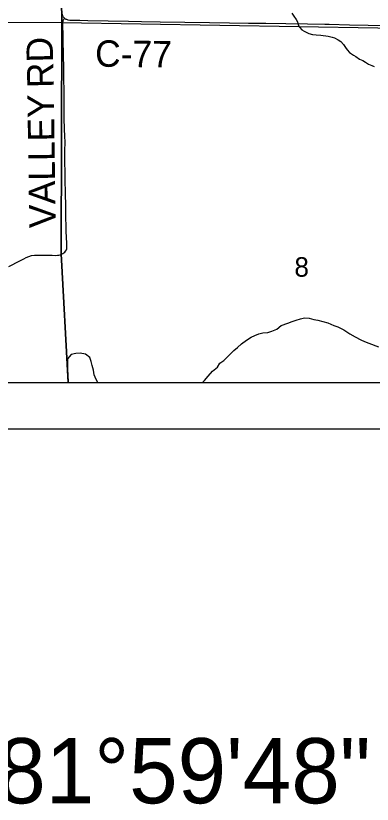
# Model space of a CAD drawing. Extents: x 0 to 34, y 0 to 22.
# Drawn here: x 6.742 to 7.507, y 13.194 to 14.887 of the extents above; entities that cross this region are included whole.
import ezdxf

# ---------------------------------------------------------------- set-up
doc = ezdxf.new("R2010")
doc.units = 0
for name, color, linetype in [('Default', 7, 'Continuous'), ('GM_X_County_Road', 7, 'Continuous'), ('GM_X_County_Road_Text', 7, 'Continuous'), ('GM_X_Minor_River', 7, 'Continuous'), ('GM_X_Section', 7, 'Continuous'), ('GM_X_Section_Text', 7, 'Continuous'), ('GM_X_State_Route', 7, 'Continuous'), ('GM_X_Township_Road', 7, 'Continuous'), ('GM_X_Township_Road_Text', 7, 'Continuous'), ('SH_Data', 7, 'Continuous'), ('SH_Text', 7, 'Continuous')]:
    doc.layers.add(name, color=color, linetype=linetype)

msp = doc.modelspace()

# ---------------------------------------------------------------- linework, layer by layer
at = {"layer": 'Default'}
for points in [[(5.6382, 14.1), (6.8542, 14.1), (6.8396, 14.3761), (6.8411, 14.8726), (5.6415, 14.8783)], [(6.8542, 14.1), (7.8747, 14.1), (7.8581, 14.855), (6.8411, 14.8726), (6.8396, 14.3761)]]:
    msp.add_lwpolyline(points, close=True, dxfattribs=at)
at = {"layer": 'GM_X_County_Road'}
for points in [[(6.8466, 14.8823), (6.8458, 14.8831), (6.8451, 14.8838), (6.8446, 14.8845), (6.8439, 14.8855), (6.8432, 14.8867), (6.8426, 14.8881), (6.842, 14.8898), (6.8416, 14.8913), (6.8412, 14.8942), (6.8409, 14.9002), (6.841, 14.9095), (6.8411, 14.956), (6.8409, 14.9747), (6.8408, 14.9965), (6.8403, 15.0307), (6.8395, 15.068), (6.8391, 15.0897), (6.8387, 15.1176), (6.8383, 15.1673), (6.8382, 15.1733), (6.8381, 15.1806)], [(6.7273, 14.3488), (6.7509, 14.361), (6.7591, 14.3657), (6.7645, 14.3685), (6.7696, 14.3705), (6.7756, 14.3722), (6.7822, 14.3732), (6.7889, 14.3735), (6.7977, 14.3734), (6.8074, 14.3733), (6.814, 14.3732), (6.82, 14.3729), (6.8264, 14.3726), (6.8313, 14.3729), (6.8342, 14.3734), (6.8375, 14.3741), (6.8403, 14.3751), (6.8429, 14.3765), (6.8451, 14.3779), (6.847, 14.3796), (6.8489, 14.3815), (6.8505, 14.3844), (6.8512, 14.3869), (6.8515, 14.391), (6.8515, 14.3982), (6.8501, 14.425), (6.8494, 14.4646), (6.8492, 14.4832), (6.849, 14.5011), (6.8485, 14.5147), (6.8479, 14.5267), (6.8478, 14.539), (6.8476, 14.5546), (6.8473, 14.5701), (6.8474, 14.5794), (6.8474, 14.5977), (6.8477, 14.6161), (6.8473, 14.6288), (6.8466, 14.6441), (6.8456, 14.6672), (6.8455, 14.6818), (6.8456, 14.6937), (6.8458, 14.7059), (6.8456, 14.7263), (6.8451, 14.7523), (6.8448, 14.78), (6.8444, 14.7976), (6.8441, 14.8114), (6.8438, 14.8269), (6.8434, 14.8485), (6.8431, 14.8637), (6.843, 14.8675), (6.8431, 14.8724), (6.8433, 14.875), (6.8439, 14.8772), (6.8442, 14.8787), (6.8448, 14.8801), (6.8456, 14.8811), (6.8466, 14.8823)], [(6.8466, 14.8823), (6.8482, 14.8812), (6.8494, 14.8805), (6.8508, 14.8799), (6.8536, 14.879), (6.8579, 14.8781), (6.864, 14.8778), (6.8688, 14.8777), (6.8791, 14.8778), (6.8968, 14.8773), (6.9403, 14.8766), (6.9838, 14.8758), (7.0117, 14.8753), (7.0521, 14.8747), (7.1048, 14.8739), (7.1576, 14.8731), (7.201, 14.8726), (7.2414, 14.8719), (7.2786, 14.8714), (7.3219, 14.8708), (7.3683, 14.8699), (7.4056, 14.8693), (7.4149, 14.8692), (7.4583, 14.8681), (7.4986, 14.8673), (7.5296, 14.8666)]]:
    msp.add_lwpolyline(points, dxfattribs=at)
at = {"layer": 'GM_X_Minor_River'}
for points in [[(7.3345, 14.8929), (7.339, 14.8868), (7.344, 14.8796), (7.3466, 14.8742), (7.3478, 14.8681), (7.3508, 14.8628), (7.3557, 14.8575), (7.3607, 14.8544), (7.3656, 14.8522), (7.3713, 14.8491), (7.3788, 14.8472), (7.3868, 14.8464), (7.397, 14.8456), (7.4019, 14.8449), (7.4072, 14.8441), (7.4129, 14.8433), (7.4213, 14.8418), (7.4262, 14.8403), (7.4338, 14.8361), (7.4395, 14.8323), (7.4455, 14.8254), (7.4497, 14.819), (7.4531, 14.814), (7.4584, 14.8087), (7.4668, 14.803), (7.4717, 14.7999), (7.48, 14.7946), (7.4872, 14.7912), (7.4925, 14.7881), (7.499, 14.7835), (7.5062, 14.7805), (7.5115, 14.7782)], [(7.143, 14.1), (7.1474, 14.1039), (7.1546, 14.1133), (7.1641, 14.124), (7.175, 14.1327), (7.1799, 14.141), (7.1886, 14.1471), (7.2098, 14.1684), (7.2181, 14.1752), (7.2268, 14.1828), (7.2374, 14.1907), (7.2469, 14.1968), (7.2552, 14.201), (7.2635, 14.2044), (7.2726, 14.2066), (7.2832, 14.207), (7.2919, 14.21), (7.3021, 14.2142), (7.3116, 14.2222), (7.3263, 14.2275), (7.3354, 14.2305), (7.3441, 14.2339), (7.3528, 14.2365), (7.3615, 14.2384), (7.3721, 14.238), (7.382, 14.2353), (7.3903, 14.2334), (7.4013, 14.2308), (7.4119, 14.2277), (7.4244, 14.222), (7.4331, 14.2193), (7.446, 14.2132), (7.4589, 14.2044), (7.4703, 14.1976), (7.4824, 14.1915), (7.4907, 14.188), (7.4995, 14.1839), (7.5207, 14.1766)], [(6.9182, 14.1), (6.9145, 14.1065), (6.9104, 14.1164), (6.9085, 14.1259), (6.9062, 14.1366), (6.9039, 14.1449), (6.9012, 14.1537), (6.8914, 14.1605), (6.8804, 14.1628), (6.8705, 14.1617), (6.8611, 14.1598), (6.8531, 14.1503), (6.8532, 14.1279), (6.8539, 14.1161), (6.8546, 14.1)]]:
    msp.add_lwpolyline(points, dxfattribs=at)
at = {"layer": 'GM_X_Section'}
for points in [[(6.8272, 15.8734), (6.8411, 14.8726), (5.6415, 14.8783), (5.6379, 15.8781), (6.7969, 15.8732)], [(6.8272, 15.8734), (7.8036, 15.873), (7.8312, 15.8725), (7.8581, 14.855), (6.8411, 14.8726)]]:
    msp.add_lwpolyline(points, close=True, dxfattribs=at)
at = {"layer": 'GM_X_State_Route'}
msp.add_lwpolyline([(7.8042, 16.2626), (7.8024, 15.8725), (6.7968, 15.8774), (5.6416, 15.8841), (5.6436, 15.468), (5.6455, 14.1), (8.9, 14.1), (8.9, 18.8876), (8.7984, 18.8872), (8.8033, 17.8763), (8.296, 17.8766), (7.7904, 17.865), (7.8038, 16.9797), (7.9972, 16.9797), (7.9972, 16.2626)], close=True, dxfattribs=at)
at = {"layer": 'GM_X_Township_Road'}
for points in [[(6.8466, 14.8823), (6.8458, 14.8831), (6.8451, 14.8838), (6.8446, 14.8845), (6.8439, 14.8855), (6.8432, 14.8867), (6.8426, 14.8881), (6.842, 14.8898), (6.8416, 14.8913), (6.8412, 14.8942), (6.8409, 14.9002), (6.841, 14.9095), (6.8411, 14.956), (6.8409, 14.9747), (6.8408, 14.9965), (6.8403, 15.0307), (6.8395, 15.068), (6.8391, 15.0897), (6.8387, 15.1176), (6.8383, 15.1673), (6.8382, 15.1733), (6.8381, 15.1806)], [(6.7273, 14.3488), (6.7509, 14.361), (6.7591, 14.3657), (6.7645, 14.3685), (6.7696, 14.3705), (6.7756, 14.3722), (6.7822, 14.3732), (6.7889, 14.3735), (6.7977, 14.3734), (6.8074, 14.3733), (6.814, 14.3732), (6.82, 14.3729), (6.8264, 14.3726), (6.8313, 14.3729), (6.8342, 14.3734), (6.8375, 14.3741), (6.8403, 14.3751), (6.8429, 14.3765), (6.8451, 14.3779), (6.847, 14.3796), (6.8489, 14.3815), (6.8505, 14.3844), (6.8512, 14.3869), (6.8515, 14.391), (6.8515, 14.3982), (6.8501, 14.425), (6.8494, 14.4646), (6.8492, 14.4832), (6.849, 14.5011), (6.8485, 14.5147), (6.8479, 14.5267), (6.8478, 14.539), (6.8476, 14.5546), (6.8473, 14.5701), (6.8474, 14.5794), (6.8474, 14.5977), (6.8477, 14.6161), (6.8473, 14.6288), (6.8466, 14.6441), (6.8456, 14.6672), (6.8455, 14.6818), (6.8456, 14.6937), (6.8458, 14.7059), (6.8456, 14.7263), (6.8451, 14.7523), (6.8448, 14.78), (6.8444, 14.7976), (6.8441, 14.8114), (6.8438, 14.8269), (6.8434, 14.8485), (6.8431, 14.8637), (6.843, 14.8675), (6.8431, 14.8724), (6.8433, 14.875), (6.8439, 14.8772), (6.8442, 14.8787), (6.8448, 14.8801), (6.8456, 14.8811), (6.8466, 14.8823)]]:
    msp.add_lwpolyline(points, dxfattribs=at)
at = {"layer": 'SH_Data'}
for p, q in [((2.1, 14.1), (8.9, 14.1)), ((2, 14), (9, 14))]:
    msp.add_line(p, q, dxfattribs=at)

# ---------------------------------------------------------------- texts
at = {"layer": 'GM_X_County_Road_Text'}
msp.add_text('C-77', height=0.05682, rotation=359.316, dxfattribs=at).set_placement((6.9119, 14.7782))
at = {"layer": 'GM_X_Section_Text'}
msp.add_text('8', height=0.0419, rotation=0, dxfattribs=at).set_placement((7.3401, 14.327))
at = {"layer": 'GM_X_Township_Road_Text'}
for s, rotation, p in [('RD', 91.4501, (6.8236, 14.733)), ('VALLEY', 90.8549, (6.8278, 14.432))]:
    msp.add_text(s, height=0.05682, rotation=rotation, dxfattribs=at).set_placement(p)
at = {"layer": 'SH_Text'}
msp.add_text('LATITUDE:  N40°45\'21"     LONGITUDE:  S81°59\'48"', height=0.14, dxfattribs=at).set_placement((3.071, 13.1958))

doc.saveas('drawing.dxf')
